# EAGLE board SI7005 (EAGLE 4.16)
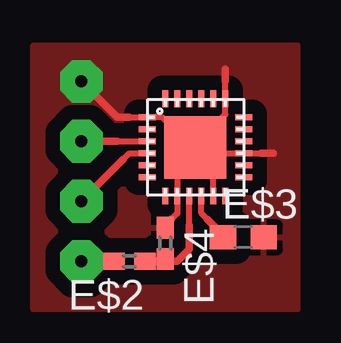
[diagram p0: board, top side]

No outline drawn. Coordinates in mm, seen from the top.
Copper layers (1*16): Top 0.035mm / dielectric 1.5mm / Bottom 0.035mm
Design rules "default": minimum track width 10mil, minimum drill 24mil, track to track 8mil, track to pad 8mil, pad to pad 8mil, via to via 8mil, smd to smd 8mil, copper to edge 40mil, drill to drill 8mil, minimum pad ring 10mil, minimum via ring 8mil, stop-mask expansion 4mil, vias tented up to drill 0mil, thermal gap 10mil

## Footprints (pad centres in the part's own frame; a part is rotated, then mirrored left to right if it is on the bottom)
QFN24NEW = smd 0.7 x 0.25: 1 -2.005,1.25; 2 -2.005,0.75; 3 -2.005,0.25; 4 -2.005,-0.25; 5 -2.005,-0.75; 6 -2.005,-1.25; 13 2.02,-1.25; 14 2.02,-0.75; 15 2.02,-0.25; 16 2.02,0.25; 17 2.02,0.75; 18 2.02,1.25 | smd 0.25 x 0.7: 7 -0.75,-2.03; 8 -0.25,-2.03; 9 0.25,-2.03; 10 0.75,-2.03; 11 1.25,-2.03; 12 -1.25,2.02; 25 -1.25,-2.03; 26 -0.75,2.02; 27 -0.25,2.02; 28 0.25,2.02; 29 0.75,2.02; 30 1.25,2.02 | smd 2.6 x 2.6: P$25 -0.005,0
C0402 = smd 0.9 x 0.7: 1 -0.65,0; 2 0.65,0
C0603 = smd 1.1 x 1: 1 -0.85,0; 2 0.85,0

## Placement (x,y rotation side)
E$1  [QFN24NEW]  6.75,6.75 0 top
E$2  [C0402]  4,2 180 top
E$3  [C0603]  8.75,3 0 top
E$4  [C0402]  5.5,2.75 270 top

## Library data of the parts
E$1 = TI_MSP430_v122
E$2-E$4 = rcl

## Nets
GND: E$3.2 E$4.1

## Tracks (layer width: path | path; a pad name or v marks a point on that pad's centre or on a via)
GND  (via drill 0.5 pad 1.78)
  Top 0.254: 4,8 4.5,8 | 8,9.5 8,8.12 7.5,7.62 | 7.5,6.5 9.5,6.5 | 5.75,3.75 6,4 6,6.5 7.5,6.5 | 7.5,5 7.5,6.5
  Top 0.305: v2,9.5 3.5,8 4,8 | 8,9.5 8,10 | 9.5,6.5 10,6.5 | 5.75,3.75 5.5,3.5
  pour Top (isolate 0.61): 0,0 0,11 11,11 11,0
S$1
  Top 0.254: 6.5,3.5 6.5,4.5
  Top 0.305: 5,2 6,2 6.5,2.5 6.5,3.5
S$2
  Top 0.254: 7.25,3.75 7,4 7,4.5
  Top 0.305: 7.25,3.75 8.12,2.88
S$3
  Top 0.254: 5,8 5.38,8 5.88,7.5
S$7  (via drill 0.5 pad 1.78)
  Top 0.305: v2,2 3,2
S$8
  Top 0.254: 3.5,7 4.5,7
  Top 0.305: 2,7 3.5,7
S$9
  Top 0.254: 3.75,6.25 4,6.5 4.5,6.5
  Top 0.305: 2,4.5 3.75,6.25
S$12  (via drill 0.5 pad 1.78)
  other vias: 2,7
S$13  (via drill 0.5 pad 1.78)
  other vias: 2,4.5

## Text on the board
Document: GND | SCL | SDA | VDD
